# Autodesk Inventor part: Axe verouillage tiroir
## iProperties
Author: Flavien MARTY
Shininess: 60.0
PropertySet Name: _Private Model Information
Created: 2001-10
Part Number: Axe verouillage tiroir
Material: Par défaut
Document SubType Name: Modélisation
Designer: Flavien MARTY
Control State: 0
Master: False
Checked Out: False
PropertySet Name: Design Tracking Control
Density: 0.0
Volumn: 0.0
Area: 0.0
PropertySet Name: Model Information
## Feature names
1. Base1
